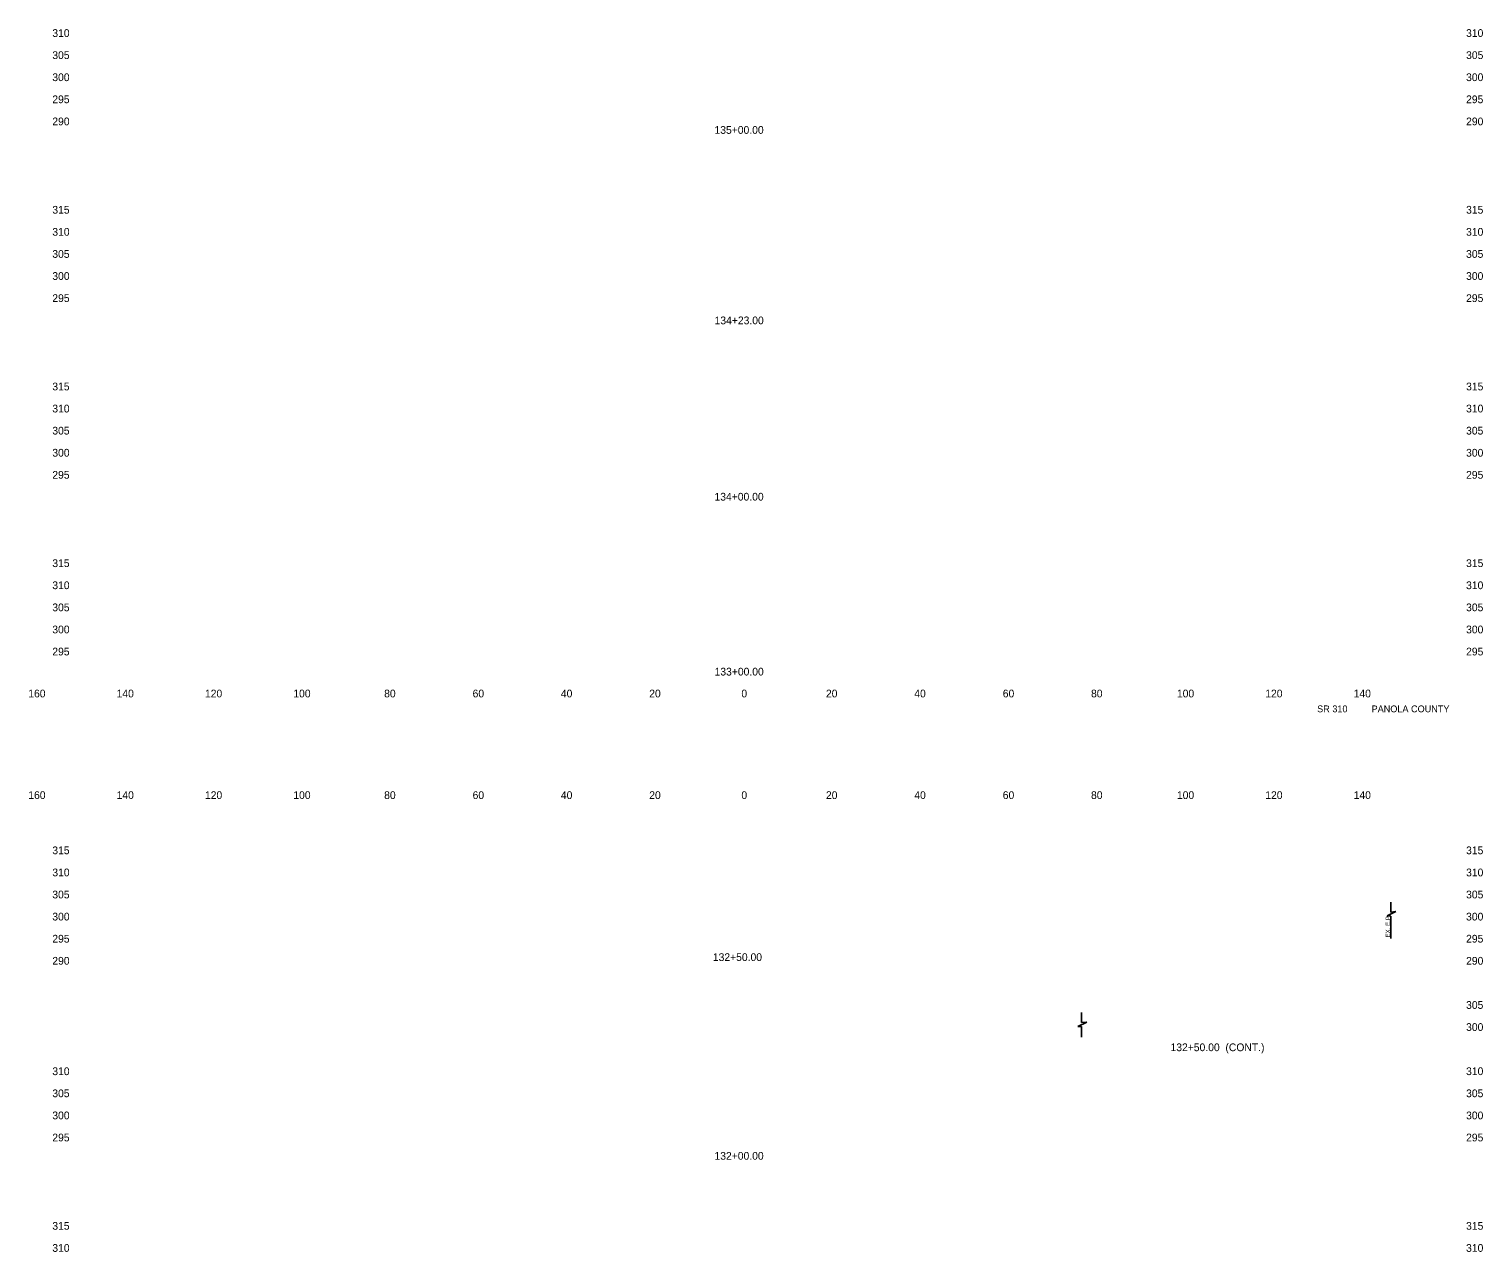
# Model space of a CAD drawing. Extents: x 21481 to 21810, y 6485 to 11067.
# Drawn here: x 21480.9 to 21809.9, y 9352.7 to 9629.5 of the extents above; entities that cross this region are included whole.
import ezdxf

# ---------------------------------------------------------------- set-up
doc = ezdxf.new("R2010")
doc.units = 0
for name, color, linetype in [('62', 7, 'Continuous'), ('XS_CELL', 7, 'Continuous'), ('XS_P_SUBGRADE_GRANULAR', 7, 'Continuous'), ('XS_P_TX_CLEARZONE', 7, 'Continuous'), ('XS_P_TX_DCH', 7, 'Continuous'), ('XS_P_TX_FS_BS', 7, 'Continuous')]:
    doc.layers.add(name, color=color, linetype=linetype)

msp = doc.modelspace()

# ---------------------------------------------------------------- linework, layer by layer
at = {"layer": 'XS_P_SUBGRADE_GRANULAR'}
for p, q in [((21789.09, 9431.86), (21789.08, 9429.62)), ((21790.27, 9429.72), (21788.27, 9428.75)), ((21788.27, 9428.75), (21789.1, 9428.72)), ((21789.08, 9429.62), (21790.27, 9429.72)), ((21789.1, 9428.72), (21789.1, 9423.63)), ((21719.09, 9406.86), (21719.08, 9404.62)), ((21720.27, 9404.72), (21718.27, 9403.75)), ((21718.27, 9403.75), (21719.1, 9403.72)), ((21719.08, 9404.62), (21720.27, 9404.72)), ((21719.1, 9403.72), (21719.1, 9401.28))]:
    msp.add_line(p, q, dxfattribs=at)

# ---------------------------------------------------------------- texts
at = {"layer": '62'}
for s, p in [('  160  ', (21479.4, 9478.21)), ('  140  ', (21499.39, 9478.21)), ('  120  ', (21519.39, 9478.21)), ('  100  ', (21539.39, 9478.21)), ('  80  ', (21559.95, 9478.21)), ('  60  ', (21579.97, 9478.21)), ('  40  ', (21599.95, 9478.21)), ('  20  ', (21619.95, 9478.21)), ('  0  ', (21640.81, 9478.21)), ('  0  ', (21640.81, 9478.21)), ('  20  ', (21659.95, 9478.21)), ('  40  ', (21679.95, 9478.21)), ('  60  ', (21699.97, 9478.21)), ('  80  ', (21719.95, 9478.21)), ('  100  ', (21739.39, 9478.21)), ('  120  ', (21759.39, 9478.21)), ('  140  ', (21779.39, 9478.21)), ('  160  ', (21479.4, 9455.21)), ('  140  ', (21499.39, 9455.21)), ('  120  ', (21519.39, 9455.21)), ('  100  ', (21539.39, 9455.21)), ('  80  ', (21559.95, 9455.21)), ('  60  ', (21579.97, 9455.21)), ('  40  ', (21599.95, 9455.21)), ('  20  ', (21619.95, 9455.21)), ('  0  ', (21640.81, 9455.21)), ('  0  ', (21640.81, 9455.21)), ('  20  ', (21659.95, 9455.21)), ('  40  ', (21679.95, 9455.21)), ('  60  ', (21699.97, 9455.21)), ('  80  ', (21719.95, 9455.21)), ('  100  ', (21739.39, 9455.21)), ('  120  ', (21759.39, 9455.21)), ('  140  ', (21779.39, 9455.21))]:
    msp.add_text(s, height=1.75, dxfattribs=at).set_placement(p)
at = {"layer": 'XS_CELL'}
for s, p in [('  310  ', (21484.84, 9627.71)), ('  310  ', (21804.84, 9627.71)), ('  305  ', (21484.84, 9622.71)), ('  305  ', (21804.84, 9622.71)), ('  300  ', (21484.84, 9617.71)), ('  300  ', (21804.84, 9617.71)), ('  295  ', (21484.84, 9612.71)), ('  295  ', (21804.84, 9612.71)), ('  290  ', (21484.84, 9607.71)), ('  290  ', (21804.84, 9607.71)), ('  315  ', (21484.84, 9587.71)), ('  315  ', (21804.84, 9587.71)), ('  310  ', (21484.84, 9582.71)), ('  310  ', (21804.84, 9582.71)), ('  305  ', (21484.84, 9577.71)), ('  305  ', (21804.84, 9577.71)), ('  300  ', (21484.84, 9572.71)), ('  300  ', (21804.84, 9572.71)), ('  295  ', (21484.84, 9567.71)), ('  295  ', (21804.84, 9567.71)), ('  315  ', (21484.84, 9547.71)), ('  315  ', (21804.84, 9547.71)), ('  310  ', (21484.84, 9542.71)), ('  310  ', (21804.84, 9542.71)), ('  305  ', (21484.84, 9537.71)), ('  305  ', (21804.84, 9537.71)), ('  300  ', (21484.84, 9532.71)), ('  300  ', (21804.84, 9532.71)), ('  295  ', (21484.84, 9527.71)), ('  295  ', (21804.84, 9527.71)), ('  315  ', (21484.84, 9507.71)), ('  315  ', (21804.84, 9507.71)), ('  310  ', (21484.84, 9502.71)), ('  310  ', (21804.84, 9502.71)), ('  305  ', (21484.84, 9497.71)), ('  305  ', (21804.84, 9497.71)), ('  300  ', (21484.84, 9492.71)), ('  300  ', (21804.84, 9492.71)), ('  295  ', (21484.84, 9487.71)), ('  295  ', (21804.84, 9487.71)), ('  315  ', (21484.84, 9442.71)), ('  315  ', (21804.84, 9442.71)), ('  310  ', (21484.84, 9437.71)), ('  310  ', (21804.84, 9437.71)), ('  305  ', (21484.84, 9432.71)), ('  305  ', (21804.84, 9432.71)), ('  300  ', (21484.84, 9427.71)), ('  300  ', (21804.84, 9427.71)), ('  295  ', (21484.84, 9422.71)), ('  295  ', (21804.84, 9422.71)), ('  290  ', (21484.84, 9417.71)), ('  290  ', (21804.84, 9417.71)), ('  305  ', (21804.84, 9407.71)), ('  300  ', (21804.84, 9402.71)), ('  310  ', (21484.84, 9392.71)), ('  310  ', (21804.84, 9392.71)), ('  305  ', (21484.84, 9387.71)), ('  305  ', (21804.84, 9387.71)), ('  300  ', (21484.84, 9382.71)), ('  300  ', (21804.84, 9382.71)), ('  295  ', (21484.84, 9377.71)), ('  295  ', (21804.84, 9377.71)), ('  315  ', (21484.84, 9357.71)), ('  315  ', (21804.84, 9357.71)), ('  310  ', (21484.84, 9352.71)), ('  310  ', (21804.84, 9352.71))]:
    msp.add_text(s, height=1.75, dxfattribs=at).set_placement(p)
at = {"layer": 'XS_P_TX_CLEARZONE'}
msp.add_text('EX. E.P.', height=1, rotation=90, dxfattribs=at).set_placement((21788.94, 9423.86))
at = {"layer": 'XS_P_TX_DCH'}
for s, p in [('  135+00.00  ', (21634.72, 9605.78)), ('  134+23.00  ', (21634.74, 9562.67)), ('  134+00.00  ', (21634.72, 9522.76)), ('  133+00.00  ', (21634.74, 9483.16)), ('  132+50.00  ', (21634.35, 9418.54)), ('  132+50.00  (CONT.)', (21737.94, 9398.13)), ('  132+00.00  ', (21634.72, 9373.56))]:
    msp.add_text(s, height=1.75, dxfattribs=at).set_placement(p)
at = {"layer": 'XS_P_TX_FS_BS'}
for s, p in [('SR 310', (21772.43, 9474.84)), ('SR 310', (21772.43, 9474.84)), ('SR 310', (21772.43, 9474.84)), ('PANOLA COUNTY', (21784.75, 9474.84)), ('PANOLA COUNTY', (21784.75, 9474.84)), ('PANOLA COUNTY', (21784.75, 9474.84))]:
    msp.add_text(s, height=1.54, dxfattribs=at).set_placement(p)

doc.saveas('drawing.dxf')
